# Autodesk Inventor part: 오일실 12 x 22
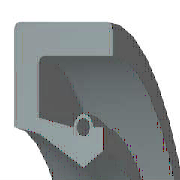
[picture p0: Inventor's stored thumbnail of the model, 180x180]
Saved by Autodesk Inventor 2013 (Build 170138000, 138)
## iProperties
IsCustomPart: 0
Created: 2015-10
Part Number: 오일실 12 x 22
Material: 고무
Description: 오일-실
Document SubType Name: Modeling
Standard: KS B 2804
Designer: mdu
Standards Organization: KS
Language: ko-KR
Size Designation: S - 12 22 7
Categories: <MemberInstance><Categories><Category DisplayName="샤프트 부품" InternalName="7f7aeb1f-a693-4053-b835-cee3144e0d98" Mnemonic="SHFT"><Category DisplayName="실링" Intern
Density: 0.93 g/cm^3
Mass: 1.0258 g
Surface Area: 17.5559 cm^2
Volume: 1.10301 cm^3
Author: mdu
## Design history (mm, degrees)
revolve "본체" stored, may be unused: angle "d17" = 90 deg
revolve "스프링1" stored, may be unused: angle "d18" = 90 deg
body "Solid1"
sketch "스케치1"
  geometry: L1 (0, 11)-(7, 11); L2 (7, 11)-(7, 9.75); L3 (7, 9.75)-(1.75, 9.75); L4 (0, 11)-(0, 8.1); L5 (0, 8.1)-(1.75, 7.75); L6 (1.75, 7.75)-(4.9, 6); L7 (4.9, 6)-(0, 6); L8 (6.3, 6.875)-(6.3, 8.1); L9 (0, 0)-(9.586, 0) reference; L10 (4.9, 6)-(6.3, 6.875); L11 (0, 18)-(0, -3) reference; L12 (-1.917, 0)-(11.503, 0) reference; L13 (4.2, 8.1)-(1.75, 8.59); L14 (1.75, 8.59)-(1.75, 9.75); L15 (6.3, 8.1)-(5.6, 8.1); C1 r 0.455 at (4.9, 8.1); A1 r 0.7 centre (4.9, 8.1) between (5.6, 8.1) and (4.2, 8.1)
  constraints: 26 end point, 5 horizontal alignment, 4 perpendicular, 2 centre point, 2 collinear, 2 horizontal, 2 parallel, 2 point on circle, 2 point on line, 2 vertical alignment, 1 coincident
  dimensions: "d0" = 22 diameter of L1 L9 (= SD2); "d1" = 13.75 diameter of L8.start L9 (= ABDM); "d2" = 1.25 distance of L1.end L2.end (computed from SD); "d3" = 0.91 diameter of C1 (= SPDI); "d4" = 1.4 diameter of A1 (= SPDA); "d5" = 12 diameter of L6.end L9 (= NND); "d6" = 15.5 diameter of L5.end L9 (= TKDM); "d7" = 16.2 diameter of L4.end L9 (= HLDM); "d8" = 4.9 distance from line of C1.centre L4 (= SPDST); "d9" = 6.3 distance between parallel lines of L8 L4 (= SDI); "d10" = 7 distance between parallel lines of L2 L4 (= SWDT); "d12" = 1.75 distance between parallel lines of L14 L4 (= SD)
fillet "모깎기1" dims "d11" = 0.3 (= RR)
other parameters: "SD2" = 22 [user parameter; used in 1 equation term], "SWDT" = 7 [user parameter; used in 1 equation term], "RR" = 0.3 [user parameter; used in 1 equation term], "SD" = 1.75 [user parameter; used in 2 equation terms], "NND" = 12 [user parameter; used in 1 equation term], "SPDA" = 1.4 [user parameter; used in 1 equation term], "SPDI" = 0.91 [user parameter; used in 1 equation term], "TKDM" = 15.5 [user parameter; used in 1 equation term], "HLDM" = 16.2 [user parameter; used in 1 equation term], "ABDM" = 13.75 [user parameter; used in 1 equation term], "SDI" = 6.3 [user parameter; used in 1 equation term], "SPDST" = 4.9 [user parameter; used in 1 equation term], "d13" = 0, "d14" = 0, "d15" = 0, "LAB" = 0.35 [user parameter]
